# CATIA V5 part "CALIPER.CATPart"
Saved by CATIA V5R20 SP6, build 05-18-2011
Part number: CALIPER
Bounding box of the stored display mesh (mm): x -152.255 to -71.099, y -828.595 to -673.52, z 46.715 to 208.577
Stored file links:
  C:\V5_education\Assemble Design\CATProduct\Disk brake\CALIPER.CATPart
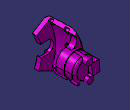
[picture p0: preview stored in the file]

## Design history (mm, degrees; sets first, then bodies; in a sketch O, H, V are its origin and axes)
Body1 "PartBody ( *SOL11 - wsp *MASTER -  )" (main body)
  Solid1 "Solid.1 (  with JELE 3575 : from *SOL11 - wsp *MASTER -  ) ( Brep from *SOL11 )": solid without history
